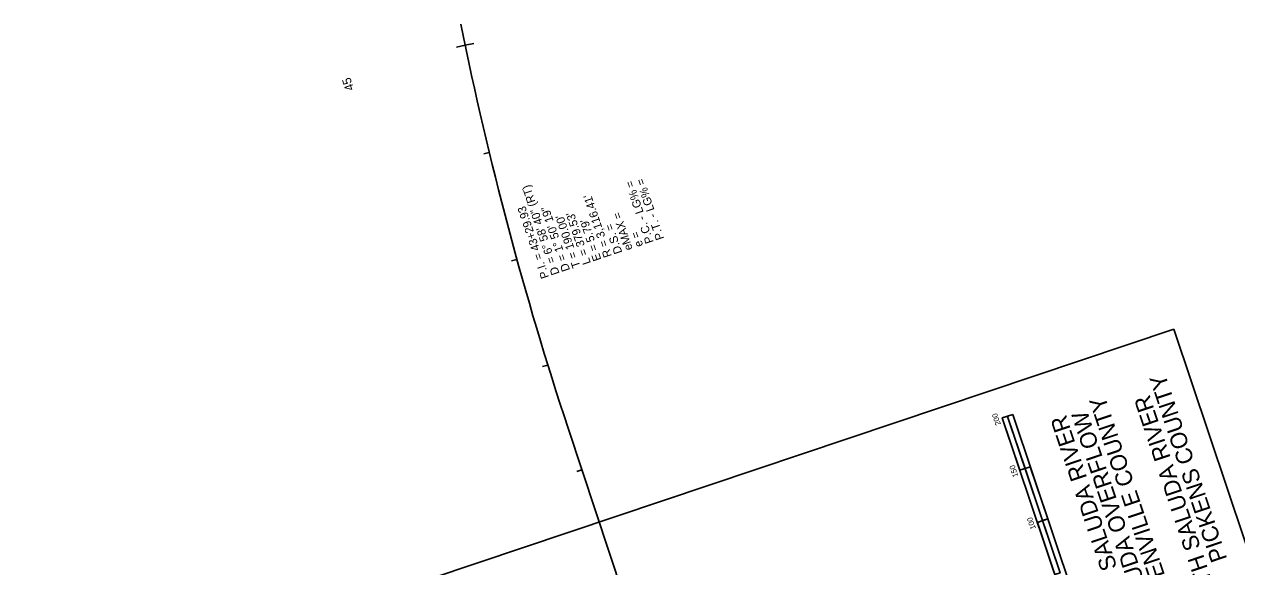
# Model space of a CAD drawing. Extents: x 1528853 to 1624411, y 1119753 to 1162242.
# Drawn here: x 1528853 to 1529953, y 1161058 to 1161550 of the extents above; entities that cross this region are included whole.
import ezdxf

# ---------------------------------------------------------------- set-up
doc = ezdxf.new("R2010")
doc.units = 0
for name, color, linetype in [('RD_HC_Cl', 7, 'Continuous'), ('RD_HC_Data', 7, 'Continuous'), ('RD_HC_Data_Tic', 7, 'Continuous'), ('RD_HC_TX_Sta50', 7, 'Continuous'), ('RD_SHT_ShtClip', 7, 'Continuous'), ('RD_SHT_TX', 7, 'Continuous')]:
    doc.layers.add(name, color=color, linetype=linetype)

msp = doc.modelspace()

# ---------------------------------------------------------------- linework, layer by layer
at = {"layer": 'RD_HC_Cl'}
msp.add_line((1529406, 1161003.2), (1529346.2, 1161183.5), dxfattribs=at)
msp.add_arc((1532304.3, 1162164.3), 3116.4, 191.3675, 198.3453, dxfattribs=at)
at = {"layer": 'RD_HC_Data_Tic'}
for p, q in [((1529260.7, 1161532.7), (1529252.9, 1161531)), ((1529252.9, 1161531), (1529245, 1161529.4)), ((1529274.8, 1161433.5), (1529269.9, 1161432.3)), ((1529299.8, 1161336.6), (1529295, 1161335.3)), ((1529327.9, 1161240.7), (1529323.1, 1161239.2)), ((1529358.8, 1161145.6), (1529354.1, 1161144))]:
    msp.add_line(p, q, dxfattribs=at)
at = {"layer": 'RD_SHT_ShtClip'}
for p, q in [((1528853, 1160923.1), (1529895.8, 1161273.1)), ((1529895.8, 1161273.1), (1530516.2, 1159424.4))]:
    msp.add_line(p, q, dxfattribs=at)
at = {"layer": 'RD_SHT_TX'}
for p, q in [((1529740.1, 1161192.6), (1529749.6, 1161195.7)), ((1529803.8, 1161003), (1529740.1, 1161192.6)), ((1529792.6, 1161052), (1529744.9, 1161194.1)), ((1529745.8, 1161194.5), (1529745.8, 1161194.5)), ((1529746.8, 1161194.8), (1529746.8, 1161194.8)), ((1529747.7, 1161195.1), (1529747.7, 1161195.1)), ((1529748.7, 1161195.4), (1529748.7, 1161195.4)), ((1529813.2, 1161006.2), (1529749.6, 1161195.7)), ((1529756.1, 1161145.2), (1529765.5, 1161148.3)), ((1529765.5, 1161148.3), (1529765.5, 1161148.3)), ((1529772, 1161097.8), (1529781.4, 1161101))]:
    msp.add_line(p, q, dxfattribs=at)
for points in [[(1529756.1, 1161145.2), (1529740.1, 1161192.6), (1529744.9, 1161194.1), (1529760.8, 1161146.8)], [(1529776.7, 1161099.4), (1529760.8, 1161146.8), (1529765.5, 1161148.3), (1529781.4, 1161101)], [(1529787.9, 1161050.4), (1529771.9, 1161097.8), (1529776.7, 1161099.4), (1529792.6, 1161052)]]:
    msp.add_lwpolyline(points, close=True, dxfattribs=at)

# ---------------------------------------------------------------- texts
at = {"layer": 'RD_HC_Data'}
for s, p in [('    = 6%%d 58\' 40" (RT)', (1529338.6, 1161323.8)), ('P.C. - LG% = ', (1529423.9, 1161352.4)), ('P.T. - LG% = ', (1529433.4, 1161355.6)), ("R = 3,116.41'", (1529386, 1161339.7)), ('P.I. = 43+29.93', (1529329.1, 1161320.6)), ('D = 1%%d 50\' 19"', (1529348.1, 1161327)), ('eMAX = ', (1529405, 1161346.1)), ("T = 190.00'", (1529357.6, 1161330.2)), ("L = 379.53'", (1529367, 1161333.3)), ("E = 5.79'", (1529376.5, 1161336.5)), ('D.S. = ', (1529395.5, 1161342.9)), ('e = ', (1529414.5, 1161349.2)), ('D', (1529338.6, 1161323.8))]:
    msp.add_text(s, height=7.5, rotation=108.5481, dxfattribs=at).set_placement(p)
at = {"layer": 'RD_HC_TX_Sta50'}
msp.add_text('45', height=8, rotation=108.568, dxfattribs=at).set_placement((1529152.3, 1161491.2))
at = {"layer": 'RD_SHT_TX'}
for s, height, rotation, p in [('PICKENS COUNTY', 15, 108.5527, (1529944.3, 1161064.7)), ('S-26 OVER TRIBUTARY TO SOUTH SALUDA RIVER', 15, 108.5527, (1530028.1, 1160753.9)), ('GREENVILLE COUNTY', 15, 108.5527, (1529901.7, 1161008.6)), ('200', 5, 108.5519, (1529738.9, 1161186.8)), ('S-40 OVER SOUTH SALUDA RIVER', 15, 108.5527, (1529903.7, 1160880.4)), ('S-40 OVER SOUTH SALUDA OVERFLOW', 15, 108.5527, (1529939.9, 1160833.6)), ('150', 5, 108.5487, (1529754.7, 1161139.8)), ('100', 5, 108.5501, (1529770.6, 1161092.4))]:
    msp.add_text(s, height=height, rotation=rotation, dxfattribs=at).set_placement(p)

doc.saveas('drawing.dxf')
